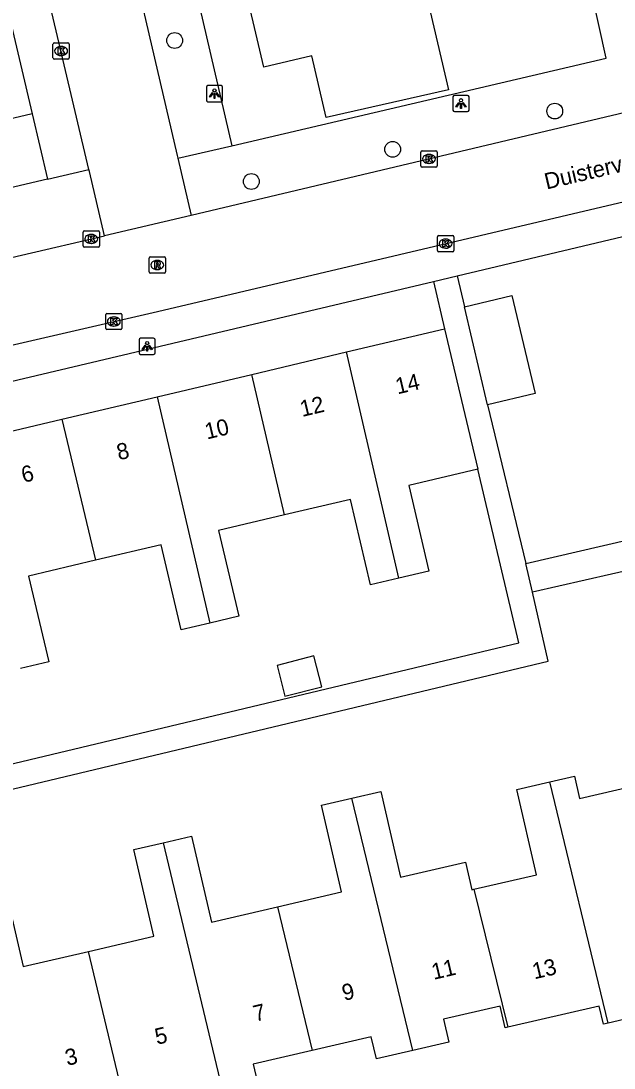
# Model space of a CAD drawing. Extents: x 158038 to 159242, y 380133 to 381214.
# Drawn here: x 158624 to 158660.6, y 380797.4 to 380862.1 of the extents above; entities that cross this region are included whole.
import ezdxf

# ---------------------------------------------------------------- set-up
doc = ezdxf.new("R2010")
doc.units = 0
for name, color, linetype in [('IMGEO_Boom', 7, 'Continuous'), ('IMGEO_Groenvoorziening', 7, 'Continuous'), ('IMGEO_Kolk', 7, 'Continuous'), ('IMGEO_Lichtpunt', 7, 'Continuous'), ('IMGEO_Openbare_ruimte_label', 7, 'Continuous'), ('IMGEO_Pand', 7, 'Continuous'), ('IMGEO_Pand_nummerreeks', 7, 'Continuous'), ('IMGEO_Parkeervlak_open', 7, 'Continuous'), ('IMGEO_Rijbaan_lokaal_open', 7, 'Continuous'), ('IMGEO_Rioolput', 7, 'Continuous'), ('IMGEO_Voetpad_open', 7, 'Continuous')]:
    doc.layers.add(name, color=color, linetype=linetype)

msp = doc.modelspace()

# ---------------------------------------------------------------- linework, layer by layer
at = {"layer": 'IMGEO_Boom'}
for centre in [(158633.474, 380860.899), (158656.976, 380856.537), (158646.955, 380854.172), (158638.218, 380852.186)]:
    msp.add_circle(centre, 0.489, dxfattribs=at)
at = {"layer": 'IMGEO_Groenvoorziening'}
msp.add_lwpolyline([(158624.66, 380856.358), (158612.909, 380853.601)], dxfattribs=at)
at = {"layer": 'IMGEO_Kolk'}
for p, q in [((158625.953, 380859.826), (158625.953, 380860.678)), ((158626.028, 380860.752), (158626.88, 380860.752)), ((158626.441, 380860.532), (158626.466, 380860.532)), ((158626.954, 380860.678), (158626.954, 380859.826)), ((158626.88, 380859.752), (158626.028, 380859.752)), ((158626.464, 380859.972), (158626.439, 380859.972)), ((158648.702, 380853.152), (158648.702, 380854.004)), ((158648.777, 380854.078), (158649.629, 380854.078)), ((158649.703, 380854.004), (158649.703, 380853.152)), ((158649.213, 380853.298), (158649.188, 380853.298)), ((158649.19, 380853.858), (158649.215, 380853.858)), ((158649.629, 380853.078), (158648.777, 380853.078)), ((158627.819, 380848.206), (158627.819, 380849.058)), ((158627.894, 380849.132), (158628.746, 380849.132)), ((158628.307, 380848.912), (158628.332, 380848.912)), ((158628.82, 380849.058), (158628.82, 380848.206)), ((158649.727, 380847.917), (158649.727, 380848.769)), ((158649.802, 380848.843), (158650.654, 380848.843)), ((158650.728, 380848.769), (158650.728, 380847.917)), ((158628.746, 380848.132), (158627.894, 380848.132)), ((158628.33, 380848.352), (158628.305, 380848.352)), ((158650.238, 380848.063), (158650.213, 380848.063)), ((158650.215, 380848.623), (158650.24, 380848.623)), ((158650.654, 380847.843), (158649.802, 380847.843)), ((158629.214, 380843.104), (158629.214, 380843.956)), ((158629.289, 380844.03), (158630.141, 380844.03)), ((158629.702, 380843.81), (158629.727, 380843.81)), ((158630.215, 380843.956), (158630.215, 380843.104)), ((158630.141, 380843.03), (158629.289, 380843.03)), ((158629.725, 380843.25), (158629.7, 380843.25))]:
    msp.add_line(p, q, dxfattribs=at)
for points in [[(158625.953, 380859.826), (158625.953, 380860.678)], [(158626.028, 380860.752), (158626.88, 380860.752)], [(158626.274, 380860.452), (158626.397, 380860.452), (158626.397, 380860.301), (158626.527, 380860.452), (158626.691, 380860.452), (158626.545, 380860.301), (158626.698, 380860.052), (158626.546, 380860.052), (158626.461, 380860.216), (158626.397, 380860.149), (158626.397, 380860.052), (158626.274, 380860.052), (158626.274, 380860.452)], [(158626.954, 380860.678), (158626.954, 380859.826)], [(158626.88, 380859.752), (158626.028, 380859.752)], [(158648.702, 380853.152), (158648.702, 380854.004)], [(158648.777, 380854.078), (158649.629, 380854.078)], [(158649.703, 380854.004), (158649.703, 380853.152)], [(158649.023, 380853.778), (158649.146, 380853.778), (158649.146, 380853.627), (158649.276, 380853.778), (158649.44, 380853.778), (158649.294, 380853.627), (158649.447, 380853.378), (158649.295, 380853.378), (158649.21, 380853.542), (158649.146, 380853.475), (158649.146, 380853.378), (158649.023, 380853.378), (158649.023, 380853.778)], [(158649.629, 380853.078), (158648.777, 380853.078)], [(158627.819, 380848.206), (158627.819, 380849.058)], [(158627.894, 380849.132), (158628.746, 380849.132)], [(158628.14, 380848.832), (158628.263, 380848.832), (158628.263, 380848.681), (158628.393, 380848.832), (158628.557, 380848.832), (158628.411, 380848.681), (158628.564, 380848.432), (158628.412, 380848.432), (158628.327, 380848.596), (158628.263, 380848.529), (158628.263, 380848.432), (158628.14, 380848.432), (158628.14, 380848.832)], [(158628.82, 380849.058), (158628.82, 380848.206)], [(158649.727, 380847.917), (158649.727, 380848.769)], [(158649.802, 380848.843), (158650.654, 380848.843)], [(158650.728, 380848.769), (158650.728, 380847.917)], [(158628.746, 380848.132), (158627.894, 380848.132)], [(158650.048, 380848.543), (158650.171, 380848.543), (158650.171, 380848.392), (158650.301, 380848.543), (158650.465, 380848.543), (158650.319, 380848.392), (158650.472, 380848.143), (158650.32, 380848.143), (158650.235, 380848.307), (158650.171, 380848.24), (158650.171, 380848.143), (158650.048, 380848.143), (158650.048, 380848.543)], [(158650.654, 380847.843), (158649.802, 380847.843)], [(158629.214, 380843.104), (158629.214, 380843.956)], [(158629.289, 380844.03), (158630.141, 380844.03)], [(158629.535, 380843.73), (158629.658, 380843.73), (158629.658, 380843.579), (158629.788, 380843.73), (158629.952, 380843.73), (158629.806, 380843.579), (158629.959, 380843.33), (158629.807, 380843.33), (158629.722, 380843.494), (158629.658, 380843.427), (158629.658, 380843.33), (158629.535, 380843.33), (158629.535, 380843.73)], [(158630.215, 380843.956), (158630.215, 380843.104)], [(158630.141, 380843.03), (158629.289, 380843.03)]]:
    msp.add_lwpolyline(points, dxfattribs=at)
for centre, start, end in [((158626.03, 380860.676), 91.55205, 178.44795), ((158626.03, 380860.676), 91.55205, 178.44795), ((158626.878, 380860.676), 1.55205, 88.44795), ((158626.878, 380860.676), 1.55205, 88.44795), ((158626.03, 380859.828), 181.55205, 268.44795), ((158626.03, 380859.828), 181.55205, 268.44795), ((158626.878, 380859.828), 271.55205, 358.44795), ((158626.878, 380859.828), 271.55205, 358.44795), ((158648.779, 380854.002), 91.55205, 178.44795), ((158648.779, 380854.002), 91.55205, 178.44795), ((158649.627, 380854.002), 1.55205, 88.44795), ((158649.627, 380854.002), 1.55205, 88.44795), ((158648.779, 380853.154), 181.55205, 268.44795), ((158648.779, 380853.154), 181.55205, 268.44795), ((158649.627, 380853.154), 271.55205, 358.44795), ((158649.627, 380853.154), 271.55205, 358.44795), ((158627.896, 380849.056), 91.55205, 178.44795), ((158627.896, 380849.056), 91.55205, 178.44795), ((158628.744, 380849.056), 1.55205, 88.44795), ((158628.744, 380849.056), 1.55205, 88.44795), ((158649.804, 380848.767), 91.55205, 178.44795), ((158649.804, 380848.767), 91.55205, 178.44795), ((158650.652, 380848.767), 1.55205, 88.44795), ((158650.652, 380848.767), 1.55205, 88.44795), ((158627.896, 380848.208), 181.55205, 268.44795), ((158627.896, 380848.208), 181.55205, 268.44795), ((158628.744, 380848.208), 271.55205, 358.44795), ((158628.744, 380848.208), 271.55205, 358.44795), ((158649.804, 380847.919), 181.55205, 268.44795), ((158649.804, 380847.919), 181.55205, 268.44795), ((158650.652, 380847.919), 271.55205, 358.44795), ((158650.652, 380847.919), 271.55205, 358.44795), ((158629.291, 380843.954), 91.55205, 178.44795), ((158629.291, 380843.954), 91.55205, 178.44795), ((158630.139, 380843.954), 1.55205, 88.44795), ((158630.139, 380843.954), 1.55205, 88.44795), ((158629.291, 380843.106), 181.55205, 268.44795), ((158629.291, 380843.106), 181.55205, 268.44795), ((158630.139, 380843.106), 271.55205, 358.44795), ((158630.139, 380843.106), 271.55205, 358.44795)]:
    msp.add_arc(centre, 0.0765, start, end, dxfattribs=at)
for centre, major_axis, ratio, start_param, end_param in [((158626.44, 380860.252), (-0.387, 0.002), 0.722429, 4.712389, 7.853982), ((158626.465, 380860.252), (-0.39, 0.002), 0.717154, 1.570796, 4.712389), ((158649.189, 380853.578), (-0.387, 0.002), 0.722429, 4.712389, 7.853982), ((158649.214, 380853.578), (-0.39, 0.002), 0.717154, 1.570796, 4.712389), ((158628.306, 380848.632), (-0.387, 0.002), 0.722429, 4.712389, 7.853982), ((158628.331, 380848.632), (-0.39, 0.002), 0.717154, 1.570796, 4.712389), ((158650.214, 380848.343), (-0.387, 0.002), 0.722429, 4.712389, 7.853982), ((158650.239, 380848.343), (-0.39, 0.002), 0.717154, 1.570796, 4.712389), ((158629.701, 380843.53), (-0.387, 0.002), 0.722429, 4.712389, 7.853982), ((158629.726, 380843.53), (-0.39, 0.002), 0.717154, 1.570796, 4.712389)]:
    msp.add_ellipse(centre, major_axis=major_axis, ratio=ratio, start_param=start_param, end_param=end_param, dxfattribs=at)
at = {"layer": 'IMGEO_Lichtpunt'}
for p, q in [((158635.441, 380858.018), (158635.441, 380857.211)), ((158635.441, 380858.018), (158635.441, 380857.211)), ((158636.343, 380858.113), (158635.535, 380858.113)), ((158636.343, 380858.113), (158635.535, 380858.113)), ((158636.437, 380857.211), (158636.437, 380858.018)), ((158636.437, 380857.211), (158636.437, 380858.018)), ((158650.679, 380857.409), (158650.679, 380856.602)), ((158650.679, 380857.409), (158650.679, 380856.602)), ((158651.581, 380857.504), (158650.773, 380857.504)), ((158651.581, 380857.504), (158650.773, 380857.504)), ((158651.675, 380856.602), (158651.675, 380857.409)), ((158651.675, 380856.602), (158651.675, 380857.409)), ((158635.535, 380857.117), (158636.343, 380857.117)), ((158635.535, 380857.117), (158636.343, 380857.117)), ((158650.773, 380856.508), (158651.581, 380856.508)), ((158650.773, 380856.508), (158651.581, 380856.508)), ((158631.275, 380842.397), (158631.275, 380841.59)), ((158631.275, 380842.397), (158631.275, 380841.59)), ((158632.177, 380842.492), (158631.369, 380842.492)), ((158632.177, 380842.492), (158631.369, 380842.492)), ((158632.271, 380841.59), (158632.271, 380842.397)), ((158632.271, 380841.59), (158632.271, 380842.397)), ((158631.369, 380841.496), (158632.177, 380841.496)), ((158631.369, 380841.496), (158632.177, 380841.496))]:
    msp.add_line(p, q, dxfattribs=at)
for points in [[(158635.815, 380857.682), (158635.854, 380857.654), (158635.666, 380857.392), (158635.628, 380857.419), (158635.815, 380857.682)], [(158635.917, 380857.634), (158635.964, 380857.634), (158635.964, 380857.312), (158635.917, 380857.312), (158635.917, 380857.634)], [(158636.027, 380857.654), (158636.065, 380857.681), (158636.252, 380857.419), (158636.213, 380857.391), (158636.027, 380857.654)], [(158651.053, 380857.073), (158651.092, 380857.045), (158650.904, 380856.783), (158650.866, 380856.81), (158651.053, 380857.073)], [(158651.155, 380857.025), (158651.202, 380857.025), (158651.202, 380856.703), (158651.155, 380856.703), (158651.155, 380857.025)], [(158651.265, 380857.045), (158651.303, 380857.072), (158651.49, 380856.81), (158651.451, 380856.782), (158651.265, 380857.045)], [(158631.649, 380842.061), (158631.688, 380842.033), (158631.5, 380841.771), (158631.462, 380841.798), (158631.649, 380842.061)], [(158631.751, 380842.013), (158631.798, 380842.013), (158631.798, 380841.691), (158631.751, 380841.691), (158631.751, 380842.013)], [(158631.861, 380842.033), (158631.899, 380842.06), (158632.086, 380841.798), (158632.047, 380841.77), (158631.861, 380842.033)]]:
    msp.add_lwpolyline(points, dxfattribs=at)
for centre in [(158635.94, 380857.816), (158651.178, 380857.207), (158631.774, 380842.195)]:
    msp.add_circle(centre, 0.0994, dxfattribs=at)
for centre, start, end in [((158635.535, 380858.018), 90, 180), ((158635.535, 380858.018), 90, 180), ((158636.343, 380858.018), 0, 90), ((158636.343, 380858.018), 0, 90), ((158635.535, 380857.211), 180, 270), ((158635.535, 380857.211), 180, 270), ((158636.343, 380857.211), 270, 0), ((158636.343, 380857.211), 270, 360), ((158650.773, 380857.409), 90, 180), ((158650.773, 380857.409), 90, 180), ((158651.581, 380857.409), 0, 90), ((158651.581, 380857.409), 0, 90), ((158650.773, 380856.602), 180, 270), ((158650.773, 380856.602), 180, 270), ((158651.581, 380856.602), 270, 0), ((158651.581, 380856.602), 270, 360), ((158631.369, 380842.397), 90, 180), ((158631.369, 380842.397), 90, 180), ((158632.177, 380842.397), 0, 90), ((158632.177, 380842.397), 0, 90), ((158631.369, 380841.59), 180, 270), ((158631.369, 380841.59), 180, 270), ((158632.177, 380841.59), 270, 0), ((158632.177, 380841.59), 270, 360)]:
    msp.add_arc(centre, 0.0946, start, end, dxfattribs=at)
at = {"layer": 'IMGEO_Pand'}
for points in [[(158646.357, 380867.318), (158648.114, 380867.718), (158649.05, 380863.685), (158650.407, 380857.841), (158642.835, 380856.148), (158641.952, 380859.946), (158638.984, 380859.249), (158637.573, 380865.32)], [(158651.393, 380844.44), (158654.322, 380845.132), (158655.756, 380839.07), (158652.827, 380838.378)], [(158652.827, 380838.378), (158651.393, 380844.44)], [(158644.109, 380841.647), (158650.164, 380843.079)], [(158650.164, 380843.079), (158651.315, 380838.214), (158652.218, 380834.399)], [(158638.247, 380840.26), (158644.109, 380841.647)], [(158647.343, 380827.659), (158644.109, 380841.647)], [(158632.387, 380838.874), (158638.247, 380840.26)], [(158640.266, 380831.571), (158638.247, 380840.26)], [(158626.506, 380837.484), (158632.387, 380838.874)], [(158632.387, 380838.874), (158635.642, 380824.882)], [(158620.666, 380836.102), (158626.506, 380837.484)], [(158626.506, 380837.484), (158628.571, 380828.767)], [(158655.185, 380828.559), (158661.688, 380830.072), (158667.001, 380831.308), (158666.065, 380835.328)], [(158652.218, 380834.399), (158647.944, 380833.388), (158649.195, 380828.097), (158647.343, 380827.659)], [(158647.343, 380827.659), (158645.589, 380827.244), (158644.337, 380832.534), (158640.266, 380831.571)], [(158640.266, 380831.571), (158636.181, 380830.604), (158637.434, 380825.306), (158635.642, 380824.882)], [(158635.642, 380824.882), (158633.881, 380824.465), (158632.636, 380829.729), (158628.571, 380828.767)], [(158628.571, 380828.767), (158624.437, 380827.789), (158625.69, 380822.495), (158623.945, 380822.082)], [(158655.594, 380826.799), (158655.185, 380828.559)], [(158662.106, 380828.273), (158655.594, 380826.799)], [(158642.088, 380822.856), (158639.804, 380822.273), (158640.293, 380820.357), (158642.577, 380820.94), (158642.088, 380822.856)], [(158651.976, 380808.429), (158655.853, 380809.326), (158654.632, 380814.602), (158656.664, 380815.072)], [(158656.664, 380815.072), (158658.189, 380815.425), (158658.508, 380814.046), (158662.847, 380815.05), (158663.432, 380812.582)], [(158660.269, 380800.159), (158656.664, 380815.072)], [(158644.438, 380814.064), (158646.221, 380814.477), (158647.446, 380809.184), (158651.456, 380810.113), (158651.852, 380808.4), (158651.976, 380808.429)], [(158639.827, 380807.345), (158643.791, 380808.262), (158642.55, 380813.627), (158644.438, 380814.064)], [(158648.201, 380798.461), (158644.438, 380814.064)], [(158628.154, 380804.587), (158632.194, 380805.522), (158630.951, 380810.889), (158632.757, 380811.307)], [(158632.757, 380811.307), (158634.516, 380811.714), (158635.746, 380806.4), (158639.827, 380807.345)], [(158632.757, 380811.307), (158636.499, 380795.71)], [(158651.976, 380808.429), (158654.075, 380799.895)], [(158639.827, 380807.345), (158641.979, 380798.463)], [(158620.165, 380804.12), (158619.725, 380806.022), (158623.374, 380806.866), (158624.117, 380803.653), (158628.154, 380804.587)], [(158630.279, 380795.697), (158628.154, 380804.587)], [(158665.887, 380802.629), (158663.356, 380802.043), (158663.614, 380800.934), (158660.269, 380800.159)], [(158654.075, 380799.895), (158653.912, 380799.857), (158653.6, 380801.204), (158650.096, 380800.393), (158650.424, 380798.976), (158648.201, 380798.461)], [(158660.269, 380800.159), (158659.981, 380800.092), (158659.723, 380801.202), (158654.075, 380799.895)], [(158648.201, 380798.461), (158645.948, 380797.94), (158645.632, 380799.309), (158641.979, 380798.463)], [(158641.979, 380798.463), (158638.327, 380797.618), (158638.653, 380796.208), (158636.499, 380795.71)]]:
    msp.add_lwpolyline(points, dxfattribs=at)
at = {"layer": 'IMGEO_Parkeervlak_open'}
for points in [[(158620.785, 380872.799), (158624.66, 380856.358)], [(158624.66, 380856.358), (158625.609, 380852.33)], [(158625.609, 380852.33), (158628.171, 380852.931)], [(158625.609, 380852.33), (158600.398, 380846.416)]]:
    msp.add_lwpolyline(points, dxfattribs=at)
at = {"layer": 'IMGEO_Rijbaan_lokaal_open'}
for points in [[(158675.929, 380925.769), (158636.891, 380916.763), (158636.843, 380917.154), (158619.873, 380913.305), (158620.128, 380912.212), (158625.512, 380888.677), (158633.627, 380853.786), (158633.666, 380853.62)], [(158628.171, 380852.931), (158619.862, 380888.097)], [(158663.759, 380857.034), (158634.489, 380850.082)], [(158604.621, 380837.745), (158632.417, 380844.154), (158677.296, 380854.712), (158677.726, 380852.891), (158684.625, 380823.643), (158679.739, 380822.539), (158683.037, 380808.743)], [(158633.666, 380853.62), (158634.489, 380850.082)], [(158629.142, 380848.822), (158628.202, 380852.801), (158628.171, 380852.931)], [(158634.489, 380850.082), (158629.142, 380848.822)], [(158603.468, 380842.85), (158629.142, 380848.822)]]:
    msp.add_lwpolyline(points, dxfattribs=at)
at = {"layer": 'IMGEO_Rioolput'}
for p, q in [((158631.9, 380846.595), (158631.9, 380847.447)), ((158631.975, 380847.521), (158632.827, 380847.521)), ((158632.901, 380847.447), (158632.901, 380846.595)), ((158632.388, 380847.301), (158632.413, 380847.301)), ((158632.827, 380846.521), (158631.975, 380846.521)), ((158632.411, 380846.741), (158632.386, 380846.741))]:
    msp.add_line(p, q, dxfattribs=at)
for points in [[(158631.9, 380846.595), (158631.9, 380847.447)], [(158631.975, 380847.521), (158632.827, 380847.521)], [(158632.901, 380847.447), (158632.901, 380846.595)], [(158632.489, 380847.219), (158632.237, 380847.221), (158632.237, 380846.821)], [(158632.237, 380846.821), (158632.361, 380846.821), (158632.361, 380846.983), (158632.372, 380846.983)], [(158632.415, 380847.14), (158632.361, 380847.14), (158632.361, 380847.059)], [(158632.361, 380847.059), (158632.413, 380847.059)], [(158632.419, 380846.954), (158632.49, 380846.821), (158632.63, 380846.821), (158632.565, 380846.947)], [(158632.827, 380846.521), (158631.975, 380846.521)]]:
    msp.add_lwpolyline(points, dxfattribs=at)
for centre, radius, start, end in [((158631.977, 380847.445), 0.0765, 91.55205, 178.44795), ((158631.977, 380847.445), 0.0765, 91.55205, 178.44795), ((158632.825, 380847.445), 0.0765, 1.55205, 88.44795), ((158632.825, 380847.445), 0.0765, 1.55205, 88.44795), ((158632.371, 380846.93), 0.0533, 26.02933, 88.69889), ((158632.397, 380847.248), 0.19, 274.7715, 282.96867), ((158632.421, 380847.044), 0.0964, 77.00612, 93.18647), ((158632.435, 380847.101), 0.0378, 276.66336, 79.67722), ((158632.488, 380847.109), 0.109, 350.36119, 89.41601), ((158632.486, 380847.109), 0.112, 277.58423, 350.98172), ((158632.47, 380846.894), 0.108, 29.51342, 73.79051), ((158631.977, 380846.597), 0.0765, 181.55205, 268.44795), ((158631.977, 380846.597), 0.0765, 181.55205, 268.44795), ((158632.825, 380846.597), 0.0765, 271.55205, 358.44795), ((158632.825, 380846.597), 0.0765, 271.55205, 358.44795)]:
    msp.add_arc(centre, radius, start, end, dxfattribs=at)
for centre, major_axis, ratio, start_param, end_param in [((158632.387, 380847.021), (-0.387, 0.002), 0.722429, 4.712389, 7.853982), ((158632.412, 380847.021), (-0.39, 0.002), 0.717154, 1.570796, 4.712389)]:
    msp.add_ellipse(centre, major_axis=major_axis, ratio=ratio, start_param=start_param, end_param=end_param, dxfattribs=at)
at = {"layer": 'IMGEO_Voetpad_open'}
for points in [[(158628.025, 380906.409), (158625.072, 380905.737), (158637.002, 380854.399)], [(158637.002, 380854.399), (158660.147, 380859.804), (158659.25, 380863.922)], [(158633.666, 380853.62), (158637.002, 380854.399)], [(158650.941, 380846.353), (158665.702, 380849.845)], [(158649.472, 380846.005), (158650.941, 380846.353)], [(158650.941, 380846.353), (158651.393, 380844.44)], [(158605.485, 380834.31), (158605.485, 380834.344), (158605.491, 380834.486), (158605.511, 380834.628), (158605.543, 380834.767), (158605.587, 380834.903), (158605.643, 380835.034), (158605.711, 380835.16), (158605.789, 380835.279), (158605.878, 380835.391), (158605.977, 380835.494), (158606.084, 380835.588), (158606.2, 380835.672), (158606.322, 380835.746), (158606.45, 380835.808), (158606.584, 380835.859), (158606.722, 380835.897), (158606.862, 380835.923), (158649.472, 380846.005)], [(158649.472, 380846.005), (158650.164, 380843.079)], [(158652.827, 380838.378), (158655.185, 380828.559)], [(158619.439, 380815.23), (158654.76, 380823.659), (158652.218, 380834.399)], [(158619.79, 380813.755), (158656.575, 380822.533), (158655.594, 380826.799)]]:
    msp.add_lwpolyline(points, dxfattribs=at)

# ---------------------------------------------------------------- texts
at = {"layer": 'IMGEO_Openbare_ruimte_label'}
msp.add_text('Duistervoorde', height=1, rotation=13.2438, dxfattribs=at).set_placement((158656.47, 380851.687))
at = {"layer": 'IMGEO_Pand_nummerreeks'}
for s, rotation, p in [('14', 13.30686, (158647.255, 380839.021)), ('12', 13.30686, (158641.357, 380837.626)), ('10', 13.30686, (158635.468, 380836.232)), ('8', 13.30686, (158630.022, 380834.945)), ('6', 13.30686, (158624.124, 380833.55)), ('11', 13.20897, (158649.484, 380802.826)), ('13', 13.03258, (158655.711, 380802.86)), ('9', 13.20897, (158643.95, 380801.527)), ('7', 13.20897, (158638.457, 380800.237)), ('5', 13.20897, (158632.38, 380798.811)), ('3', 13.20897, (158626.832, 380797.508))]:
    msp.add_text(s, height=1, rotation=rotation, dxfattribs=at).set_placement(p)

doc.saveas('drawing.dxf')
